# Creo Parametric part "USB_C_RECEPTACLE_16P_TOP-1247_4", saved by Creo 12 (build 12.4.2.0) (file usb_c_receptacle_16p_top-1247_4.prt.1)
Units: Custom; MM, KILOGRAM, SECS

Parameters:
  PTC_WM_ITERATION = "0"
  PTC_WM_VERSION = "-.0"
  PTC_WM_LIFECYCLE_STATE = "In Work"
  PTC_WM_LIFECYCLE = "MO_CADDocument"
  PTC_WM_CREATED_BY = "Maximilian Roepper (Z0017RMS: MO)"
  PTC_WM_CREATED_ON = "18-Sep-26 11:36:42 AM"
  PTC_WM_MODIFIED_BY = "Maximilian Roepper (Z0017RMS: MO)"
  PTC_WM_MODIFIED_ON = "18-Sep-26 11:36:46 AM"
  PDMLINKNUMBER = "PDM000071455050"
  PTC_WM_NAME = "usb_c_receptacle_16p_top-1247_4.prt"
  PTC_WM_NUMBER = "PDM000071455050"

Other parameters: WEIGHT, WEIGHT_FACTOR, WEIGHT_ADD, _MASS_TEMP, _DIFF_TEMP, MC_ERRORS, SUPPLIER

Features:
  1. coordinate system
  2. datum plane "PRT_YZ"
  3. datum plane "PRT_XY"
  4. datum plane "PRT_XZ"
  5. coordinate system
  6. datum axis
  7. datum axis
  8. datum axis
  9. coordinate system
  10. imported feature
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
Other named items: PRT, SIEMENS_MO, DRW_VIEW_ORG, PRT_X, PRT_Y, PRT_Z, CS0, ROUGH_GROB

Layers: 00_STD_CSYS-KSYS, 01_STD_PLANES-EBENEN, 02_STD_AXES-ACHSEN, 03_STD_CSYS-KSYS, 24_IMPORT_FEAT-IMPORT_KE

Surfaces: 5 plane, 1 cylinder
